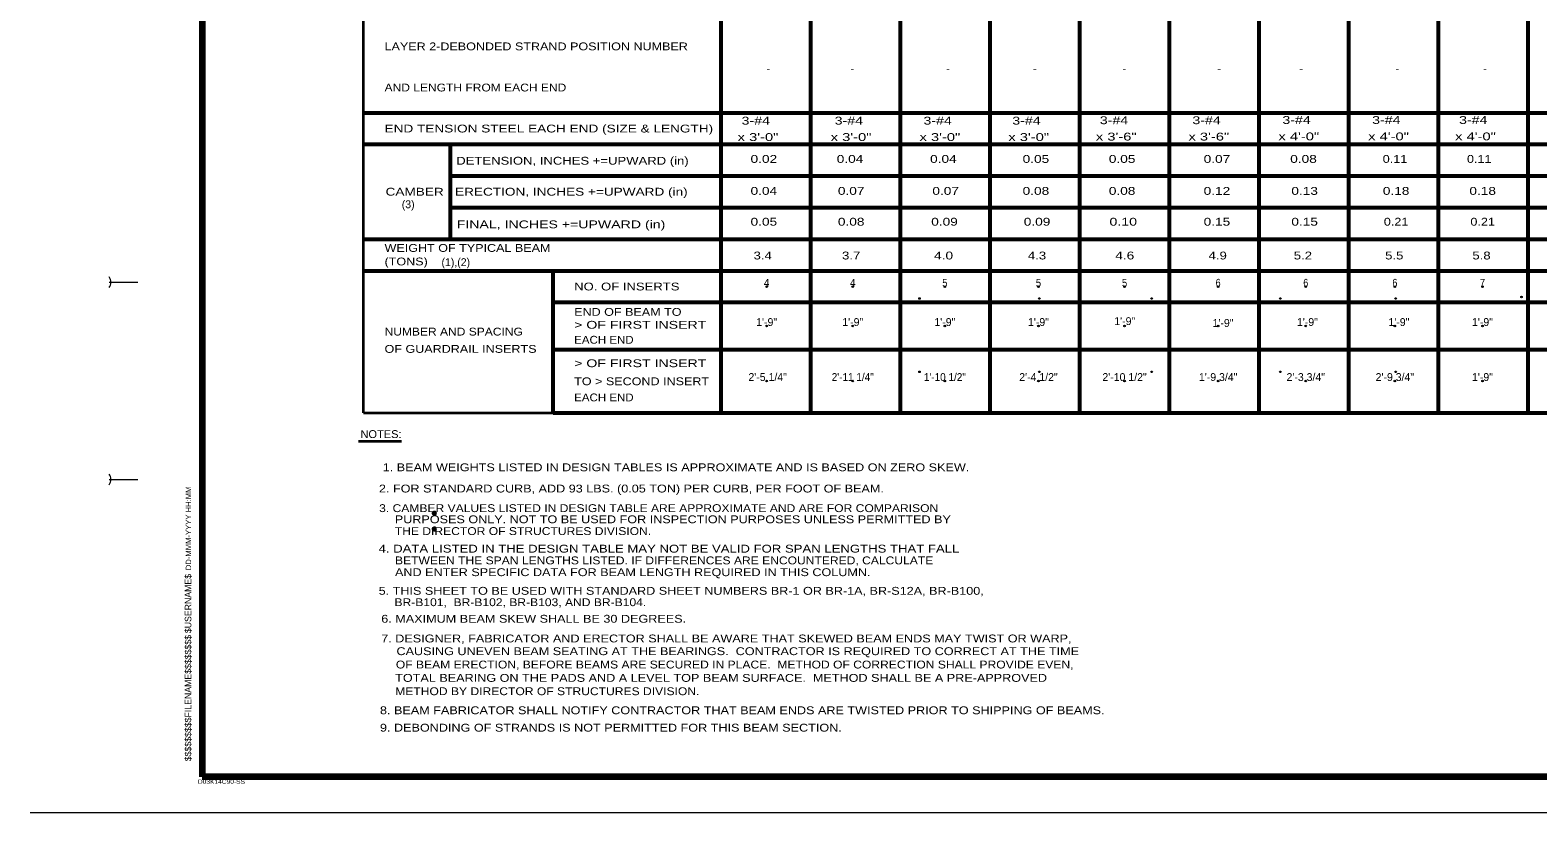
# Model space of a CAD drawing. Extents: x 758 to 1184, y 2441 to 2716.
# Drawn here: x 758.5 to 1021.3, y 2441.1 to 2577.5 of the extents above; entities that cross this region are included whole.
import ezdxf
from ezdxf.enums import TextEntityAlignment as Align

# ---------------------------------------------------------------- set-up
doc = ezdxf.new("R2010")
doc.units = 0
doc.header["$LTSCALE"] = 0.55
doc.header["$PDMODE"] = 32
doc.header["$PDSIZE"] = 0.275
for name, color, linetype, lineweight in [('1', 7, 'Continuous', 25), ('17', 7, 'Continuous', 53), ('20', 7, 'Continuous', 13), ('61', 7, 'Continuous', 13), ('7', 7, 'Continuous', 53)]:
    doc.layers.add(name, color=color, linetype=linetype, lineweight=lineweight)
doc.layers.add('21', color=7, linetype='Continuous')

msp = doc.modelspace()

# ---------------------------------------------------------------- linework, layer by layer
at = {"layer": '17'}
msp.add_lwpolyline([(849.6756, 2510.7871), (849.6756, 2521.7996), (849.6756, 2530.0621), (849.6756, 2535.5621)], dxfattribs=at)
at = {"layer": '20'}
for p in [(886.8967, 2532.7745), (901.9042, 2532.7745), (913.5413, 2530.719), (917.9579, 2532.7745), (934.2732, 2532.7745), (934.4227, 2530.719), (949.2807, 2532.7745), (953.9962, 2530.719), (965.5959, 2532.7745), (976.4469, 2530.719), (980.8649, 2532.7745), (996.3955, 2532.7745), (996.5436, 2530.719), (1011.6646, 2532.7745), (1018.4712, 2530.9808), (886.8967, 2525.9246), (901.9042, 2525.9246), (917.9579, 2525.9246), (934.2732, 2525.9246), (949.2807, 2525.9246), (965.5959, 2525.9246), (980.8649, 2525.9246), (996.3955, 2525.9246), (1011.6646, 2525.9246), (913.5413, 2517.933), (934.4227, 2517.933), (953.9962, 2517.933), (976.4469, 2517.933), (996.5436, 2517.933), (886.8967, 2516.3349), (901.9042, 2516.3349), (917.9579, 2516.3349), (934.2732, 2516.3349), (949.2807, 2516.3349), (965.5959, 2516.3349), (980.8649, 2516.3349), (996.3955, 2516.3349), (1011.6646, 2516.3349)]:
    msp.add_point(p, dxfattribs=at)
at = {"layer": '61', "lineweight": 158}
for p in [(788.5283, 2709.8172), (1177.2783, 2447.3172)]:
    msp.add_line(p, (788.5283, 2447.3172), dxfattribs=at)
at = {"layer": '61'}
for p, q in [((772.2783, 2533.5672), (777.2783, 2533.5672)), ((772.2783, 2499.1797), (777.2783, 2499.1797)), ((1183.5658, 2441.0547), (758.5283, 2441.0547))]:
    msp.add_line(p, q, dxfattribs=at)
for centre, start, end in [((771.0293, 2533.5596), 322.67175, 36.41154), ((771.0293, 2499.1846), 323.13009, 36.86989)]:
    msp.add_arc(centre, 1.5625, start, end, dxfattribs=at)
at = {"layer": '7'}
for p, q in [((879.0006, 2510.7871), (879.0006, 2662.2371)), ((894.6256, 2510.7871), (894.6256, 2662.2371)), ((910.2506, 2510.7871), (910.2506, 2662.2371)), ((925.8756, 2510.7871), (925.8756, 2662.2371)), ((941.5006, 2510.7871), (941.5006, 2662.2371)), ((957.1256, 2510.7871), (957.1256, 2662.2371)), ((972.7506, 2510.7871), (972.7506, 2662.2371)), ((988.3756, 2510.7871), (988.3756, 2662.2371)), ((1004.0006, 2510.7871), (1004.0006, 2662.2371)), ((1019.6256, 2510.7871), (1019.6256, 2662.2371)), ((816.6381, 2563.0996), (1144.6256, 2563.0996)), ((816.6381, 2557.5996), (1144.6256, 2557.5996)), ((831.7881, 2541.0746), (831.7881, 2557.6121)), ((831.7881, 2552.0871), (1144.6256, 2552.0871)), ((831.7881, 2546.5871), (1144.6256, 2546.5871)), ((816.6381, 2541.0746), (1144.6256, 2541.0746)), ((816.6381, 2535.5621), (1144.6256, 2535.5621)), ((849.6756, 2530.0621), (1144.6256, 2530.0621)), ((849.6756, 2521.7996), (1144.6256, 2521.7996)), ((849.6756, 2510.7871), (1144.6256, 2510.7871))]:
    msp.add_line(p, q, dxfattribs=at)
at = {"layer": '7', "lineweight": 35}
for p, q in [((816.6381, 2562.5871), (816.6381, 2581.3621)), ((816.6381, 2510.7871), (849.6756, 2510.7871)), ((816.6381, 2510.7871), (860.6881, 2510.7871)), ((815.7847, 2505.8566), (823.2712, 2505.8566))]:
    msp.add_line(p, q, dxfattribs=at)
msp.add_lwpolyline([(816.6381, 2510.7871), (816.6381, 2537.5121), (816.6381, 2562.5871)], dxfattribs=at)
at = {"layer": '7', "lineweight": 13}
msp.add_lwpolyline([(934.1256, 2510.7871), (934.1256, 2510.7871), (879.0506, 2510.7871), (879.0506, 2510.7871)], close=True, dxfattribs=at)
msp.add_lwpolyline([(934.1256, 2510.7871), (934.1256, 2510.7871), (879.0506, 2510.7871), (879.0506, 2510.7871)], close=True, dxfattribs=at)
at = {"layer": '7'}
for p in [(828.9862, 2493.2882), (828.9862, 2490.5503)]:
    msp.add_point(p, dxfattribs=at)

# ---------------------------------------------------------------- texts
at = {"layer": '1', "width": 1.05}
msp.add_text('DD-MMM-YYYY HH:MM', height=0.949, rotation=90, dxfattribs=at).set_placement((786.5908, 2483.3547))
at = {"layer": '1'}
for s, p in [('$USERNAME$', (786.6158, 2472.3797)), ('$$$$$$$$$FILENAME$$$$$$$$', (786.6158, 2450.0547))]:
    msp.add_text(s, height=1.139, rotation=90, dxfattribs=at).set_placement(p)
at = {"layer": '20'}
for s, width, p in [('-', 1.1, (887.2062, 2570.0737)), ('-', 1.1, (901.8318, 2570.0737)), ('-', 1.1, (918.4974, 2570.0737)), ('-', 1.1, (933.6357, 2570.0737)), ('-', 1.1, (949.2551, 2570.0737)), ('-', 1.1, (965.7846, 2570.0737)), ('-', 1.1, (980.0755, 2570.0737)), ('-', 1.1, (996.8142, 2570.0737)), ('-', 1.1, (1012.0989, 2570.0737)), ('0.02', 1.3, (886.4112, 2554.3585)), ('0.04', 1.3, (901.4342, 2554.3585)), ('0.04', 1.3, (917.7023, 2554.3585)), ('0.05', 1.3, (933.8344, 2554.3585)), ('0.05', 1.3, (948.8575, 2554.3585)), ('0.07', 1.3, (965.3871, 2554.3585)), ('0.08', 1.3, (980.473, 2554.3585)), ('0.11', 1.2, (996.4166, 2554.3585)), ('0.11', 1.2, (1011.105, 2554.3585)), ('0.04', 1.3, (886.4112, 2548.7887)), ('0.07', 1.3, (901.6331, 2548.7887)), ('0.07', 1.3, (918.0998, 2548.7887)), ('0.08', 1.3, (933.8344, 2548.7887)), ('0.08', 1.3, (948.8575, 2548.7887)), ('0.12', 1.3, (965.3871, 2548.7887)), ('0.13', 1.3, (980.6717, 2548.7887)), ('0.18', 1.3, (996.6153, 2548.7887)), ('0.18', 1.3, (1011.7013, 2548.7887)), ('0.05', 1.3, (886.4112, 2543.4175)), ('0.08', 1.3, (901.6331, 2543.4175)), ('0.09', 1.3, (917.9011, 2543.4175)), ('0.09', 1.3, (934.0332, 2543.4175)), ('0.10', 1.35, (949.0562, 2543.4175)), ('0.15', 1.3, (965.3871, 2543.4175)), ('0.15', 1.3, (980.6717, 2543.4175)), ('0.21', 1.2, (996.6153, 2543.4175)), ('0.21', 1.2, (1011.7013, 2543.4175)), ('3.4', 1.25, (886.2124, 2537.5252)), ('3.7', 1.25, (901.6331, 2537.5252)), ('4.0', 1.3, (917.7396, 2537.5252)), ('4.3', 1.25, (934.0262, 2537.5252)), ('4.6', 1.3, (949.3229, 2537.5252)), ('4.9', 1.25, (965.5194, 2537.5252)), ('5.2', 1.25, (980.3662, 2537.5252)), ('5.5', 1.25, (996.2928, 2537.5252)), ('5.8', 1.25, (1011.4996, 2537.5252)), ('4', 0.95, (886.9022, 2532.7745)), ('4', 0.95, (901.9097, 2532.7745)), ('5', 0.9, (917.9635, 2532.7745)), ('5', 0.9, (934.2789, 2532.7745)), ('5', 0.9, (949.2864, 2532.7745)), ('6', 0.85, (965.596, 2532.7745)), ('6', 0.85, (980.8706, 2532.7745)), ('6', 0.85, (996.4012, 2532.7745)), ('7', 0.9, (1011.6703, 2532.7745)), ('2\'-11 1/4"', 0.95, (901.9042, 2516.3349)), ('1\'-10 1/2"', 0.95, (917.9579, 2516.3349))]:
    msp.add_text(s, height=1.37, dxfattribs=dict(at, width=width)).set_placement(p, align=Align.CENTER)
for s, width, p in [(' 3-#4', 1.35, (881.8393, 2561.0327)), (' 3-#4', 1.35, (898.0612, 2561.0327)), (' 3-#4', 1.35, (913.5421, 2561.0327)), (' 3-#4', 1.35, (929.0229, 2561.0327)), (' 3-#4', 1.35, (944.2857, 2561.1073)), (' 3-#4', 1.35, (960.4177, 2561.1073)), (' 3-#4', 1.35, (976.0999, 2561.1473)), (' 3-#4', 1.35, (991.7455, 2561.1473)), (' 3-#4', 1.35, (1006.8969, 2561.1473)), ('x 3\'-6"', 1.4, (944.2857, 2558.2531)), ('x 3\'-6"', 1.4, (960.4177, 2558.2531)), ('x 4\'-0"', 1.4, (976.0999, 2558.2932)), ('x 4\'-0"', 1.4, (991.7455, 2558.2932)), ('x 4\'-0"', 1.4, (1006.8969, 2558.2932)), ('x 3\'-0"', 1.4, (881.8393, 2558.1785)), ('x 3\'-0"', 1.4, (898.0612, 2558.1785)), ('x 3\'-0"', 1.4, (913.5421, 2558.1785)), ('x 3\'-0"', 1.4, (929.0229, 2558.1785))]:
    msp.add_text(s, height=1.37, dxfattribs=dict(at, width=width)).set_placement(p)
for s, p in [('1\'-9"', (886.8966, 2525.9246)), ('1\'-9"', (901.9042, 2525.9246)), ('1\'-9"', (917.9579, 2525.9246)), ('1\'-9"', (934.2731, 2525.9246)), ('1\'-9"', (949.3126, 2526.0859)), ('1\'-9"', (966.445, 2525.7632)), ('1\'-9"', (981.152, 2525.9246)), ('1\'-9"', (997.1045, 2525.9246)), ('1\'-9"', (1011.6645, 2525.9246)), ('2\'-5 1/4"', (887.0715, 2516.3349)), ('2\'-4 1/2"', (934.2734, 2516.3349)), ('2\'-10 1/2"', (949.2806, 2516.3349)), ('1\'-9 3/4"', (965.5959, 2516.3349)), ('2\'-3 3/4"', (980.8652, 2516.3349)), ('2\'-9 3/4"', (996.3954, 2516.3349)), ('1\'-9"', (1011.6645, 2516.3349))]:
    msp.add_text(s, height=1.37, dxfattribs=at).set_placement(p, align=Align.CENTER)
at = {"layer": '21'}
for s, p in [('(3)', (824.4181, 2546.4564)), ('(1),(2)', (832.7187, 2536.3696))]:
    msp.add_text(s, height=1.37, dxfattribs=at).set_placement(p, align=Align.CENTER)
for s, height, width, p in [('NOTES:', 1.37, 1.05, (816.102, 2506.3922)), ('1. BEAM WEIGHTS LISTED IN DESIGN TABLES IS APPROXIMATE AND IS BASED ON ZERO SKEW.', 1.37, 1.2, (819.9769, 2500.6028)), ('5. THIS SHEET TO BE USED WITH STANDARD SHEET NUMBERS BR-1 OR BR-1A, BR-S12A, BR-B100,', 1.369, 1.2, (819.2721, 2479.0718)), ('BR-B101,  BR-B102, BR-B103, AND BR-B104.', 1.369, 1.15, (822.0316, 2477.0871)), ('6. MAXIMUM BEAM SKEW SHALL BE 30 DEGREES.', 1.37, 1.2, (819.722, 2474.1998)), ('7. DESIGNER, FABRICATOR AND ERECTOR SHALL BE AWARE THAT SKEWED BEAM ENDS MAY TWIST OR WARP,', 1.37, 1.2, (819.722, 2470.7653)), ('OF BEAM ERECTION, BEFORE BEAMS ARE SECURED IN PLACE.  METHOD OF CORRECTION SHALL PROVIDE EVEN,', 1.37, 1.15, (822.2682, 2466.2231)), ('CAUSING UNEVEN BEAM SEATING AT THE BEARINGS.  CONTRACTOR IS REQUIRED TO CORRECT AT THE TIME', 1.37, 1.2, (822.3788, 2468.5496)), ('TOTAL BEARING ON THE PADS AND A LEVEL TOP BEAM SURFACE.  METHOD SHALL BE A PRE-APPROVED', 1.37, 1.2, (822.1574, 2463.8966)), ('METHOD BY DIRECTOR OF STRUCTURES DIVISION.', 1.37, 1.15, (822.1574, 2461.5701)), ('8. BEAM FABRICATOR SHALL NOTIFY CONTRACTOR THAT BEAM ENDS ARE TWISTED PRIOR TO SHIPPING OF BEAMS.', 1.37, 1.2, (819.5006, 2458.2465)), ('9. DEBONDING OF STRANDS IS NOT PERMITTED FOR THIS BEAM SECTION.', 1.37, 1.2, (819.5006, 2455.2147))]:
    msp.add_text(s, height=height, dxfattribs=dict(at, width=width)).set_placement(p)
at = {"layer": '61', "width": 1.15}
msp.add_text('D03K14C90-SS', height=0.7498, dxfattribs=at).set_placement((787.7658, 2446.1172))
at = {"layer": '7'}
for s, height, width, p in [('LAYER 2-DEBONDED STRAND POSITION NUMBER', 1.363, 1.2, (820.3006, 2573.9871)), ('AND LENGTH FROM EACH END', 1.363, 1.15, (820.3006, 2566.8121)), ('END TENSION STEEL EACH END (SIZE & LENGTH)', 1.363, 1.3, (820.3006, 2559.6621)), ('DETENSION, INCHES +=UPWARD (in)', 1.363, 1.25, (832.8006, 2554.0496)), ('CAMBER   ERECTION, INCHES +=UPWARD (in)', 1.363, 1.3, (820.4756, 2548.6496)), ('FINAL, INCHES +=UPWARD (in)', 1.363, 1.35, (832.8756, 2542.9621)), ('WEIGHT OF TYPICAL BEAM', 1.363, 1.2, (820.3006, 2538.8496)), ('(TONS)', 1.363, 1.2, (820.3006, 2536.4871)), ('NO. OF INSERTS', 1.363, 1.25, (853.3506, 2532.1246)), ('END OF BEAM TO', 1.363, 1.2, (853.3506, 2527.6996)), ('NUMBER AND SPACING', 1.363, 1.15, (820.3006, 2524.2621)), ('> OF FIRST INSERT', 1.363, 1.35, (853.3506, 2525.4496)), ('EACH END', 1.363, 1.1, (853.3506, 2522.8371)), ('OF GUARDRAIL INSERTS', 1.363, 1.2, (820.3006, 2521.2496)), ('> OF FIRST INSERT', 1.363, 1.35, (853.3506, 2518.7496)), ('TO > SECOND INSERT', 1.363, 1.2, (853.3506, 2515.5996)), ('EACH END', 1.363, 1.1, (853.3506, 2512.7871)), ('2. FOR STANDARD CURB, ADD 93 LBS. (0.05 TON) PER CURB, PER FOOT OF BEAM.', 1.369, 1.2, (819.3231, 2496.9033)), ('3. CAMBER VALUES LISTED IN DESIGN TABLE ARE APPROXIMATE AND ARE FOR COMPARISON', 1.369, 1.15, (819.3577, 2493.4845)), ('PURPOSES ONLY. NOT TO BE USED FOR INSPECTION PURPOSES UNLESS PERMITTED BY', 1.369, 1.2, (822.0887, 2491.5393)), ('THE DIRECTOR OF STRUCTURES DIVISION.', 1.369, 1.15, (822.0887, 2489.4859)), ('4. DATA LISTED IN THE DESIGN TABLE MAY NOT BE VALID FOR SPAN LENGTHS THAT FALL', 1.369, 1.25, (819.262, 2486.4233)), ('AND ENTER SPECIFIC DATA FOR BEAM LENGTH REQUIRED IN THIS COLUMN.', 1.369, 1.2, (822.124, 2482.3227)), ('BETWEEN THE SPAN LENGTHS LISTED. IF DIFFERENCES ARE ENCOUNTERED, CALCULATE', 1.369, 1.15, (822.124, 2484.3754))]:
    msp.add_text(s, height=height, dxfattribs=dict(at, width=width)).set_placement(p)

doc.saveas('drawing.dxf')
